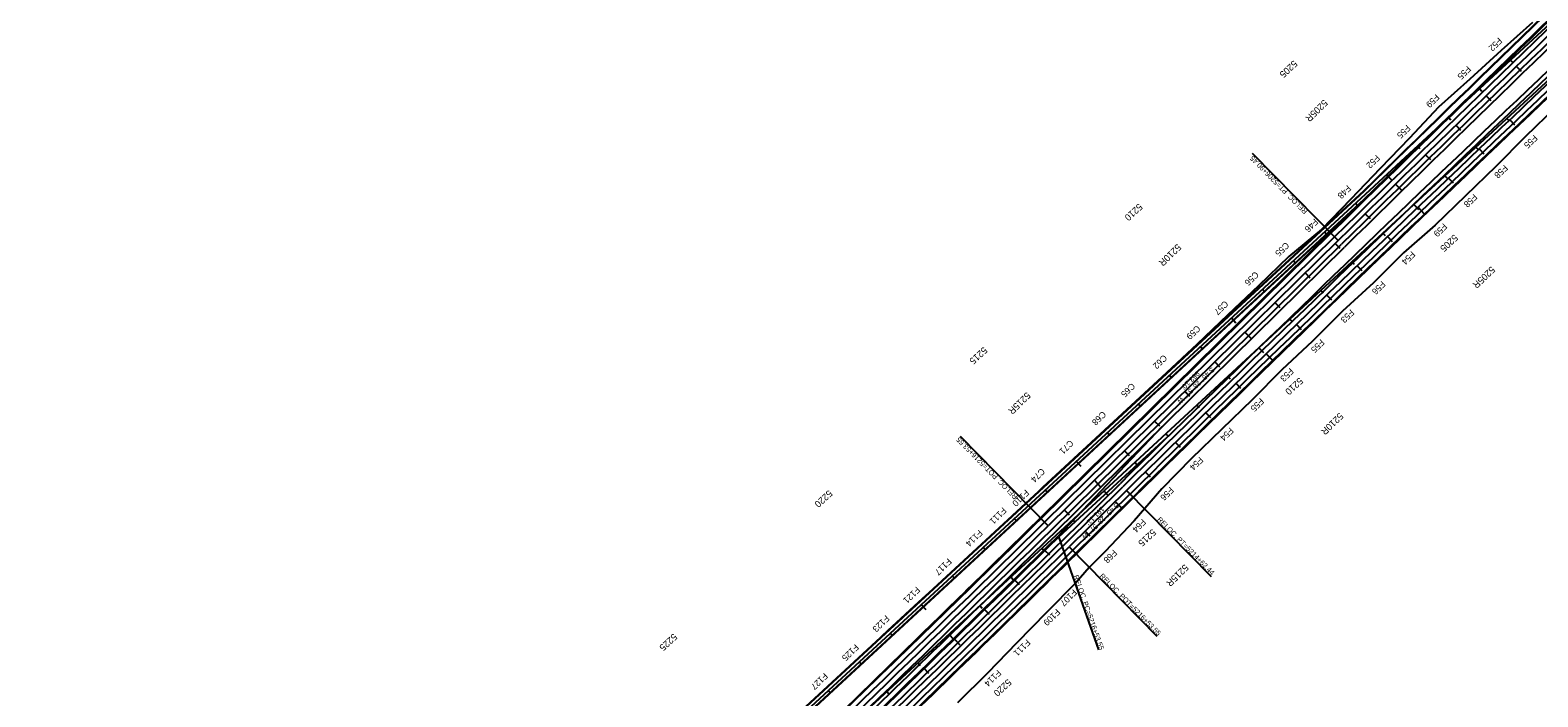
# Model space of a CAD drawing. Extents: x 2160877 to 2175861, y 601747 to 617724.
# Drawn here: x 2166538 to 2170110, y 610271 to 611849 of the extents above; entities that cross this region are included whole.
import ezdxf

# ---------------------------------------------------------------- set-up
doc = ezdxf.new("R2010")
doc.units = 0
for name, color, linetype in [('RD_HC_Cl', 7, 'Continuous'), ('RD_HC_CL_Rel', 7, 'Continuous'), ('RD_HC_Data_Rel', 7, 'Continuous'), ('RD_HC_Data_Tic', 7, 'Continuous'), ('RD_HC_Data_Tic_Rel', 7, 'Continuous'), ('RD_HC_TX_Rel_Sta50', 7, 'Continuous'), ('RD_HC_TX_Rel_StaOther', 7, 'Continuous'), ('RD_HC_TX_StaOther', 7, 'Continuous'), ('RD_PD_CstnLmt', 7, 'Continuous'), ('RD_PD_CstnLmt_TX', 7, 'Continuous'), ('RD_PD_Final_LnLine', 7, 'Continuous'), ('RD_PD_Final_TrvlWay', 7, 'Continuous'), ('RD_PD_GR', 7, 'Continuous'), ('RD_PD_MedBWall', 7, 'Continuous')]:
    doc.layers.add(name, color=color, linetype=linetype)

msp = doc.modelspace()

# ---------------------------------------------------------------- linework, layer by layer
at = {"layer": 'RD_HC_Cl'}
for p, q in [((2172207.3, 613775.1), (2163672.2, 605893.8)), ((2172272.5, 613704.6), (2163737.4, 605823.3))]:
    msp.add_line(p, q, dxfattribs=at)
at = {"layer": 'RD_HC_CL_Rel'}
for p, q in [((2169636.8, 611351.3), (2168950.1, 610676)), ((2169135.7, 610759.9), (2168999.4, 610625.9))]:
    msp.add_line(p, q, dxfattribs=at)
for centre, radius, start, end in [((2222221.5, 557873.6), 75000, 132.719474, 134.517591), ((2219616.9, 559421.3), 72000, 132.719474, 134.517591), ((2118143, 662346), 72500, 312.719474, 314.517591)]:
    msp.add_arc(centre, radius, start, end, dxfattribs=at)
at = {"layer": 'RD_HC_Data_Rel'}
for p, q in [((2169636.8, 611351.3), (2169434.4, 611557.2)), ((2168950.1, 610676), (2168742.3, 610887.4)), ((2169135.7, 610759.9), (2169336.4, 610555.8)), ((2168974.8, 610650.9), (2169069, 610382.3)), ((2168999.4, 610625.9), (2169207.3, 610414.5))]:
    msp.add_line(p, q, dxfattribs=at)
at = {"layer": 'RD_HC_Data_Tic'}
for p, q in [((2170045.3, 611778.7), (2170050.7, 611772.8)), ((2169971.8, 611710.9), (2169977.3, 611705)), ((2169898.4, 611643), (2169903.8, 611637.2)), ((2170037, 611640.3), (2170042.4, 611634.5)), ((2169824.9, 611575.2), (2169830.3, 611569.3)), ((2169963.5, 611572.5), (2169968.9, 611566.6)), ((2169751.4, 611507.4), (2169762.3, 611495.6)), ((2169890, 611504.7), (2169895.4, 611498.8)), ((2169678, 611439.5), (2169683.4, 611433.6)), ((2169816.5, 611436.8), (2169827.4, 611425.1)), ((2169604.5, 611371.7), (2169609.9, 611365.8)), ((2169743.1, 611369), (2169748.5, 611363.1)), ((2169531, 611303.8), (2169536.4, 611298)), ((2169669.6, 611301.1), (2169675, 611295.3)), ((2169457.5, 611236), (2169463, 611230.1)), ((2169596.1, 611233.3), (2169601.6, 611227.4)), ((2169384.1, 611168.1), (2169394.9, 611156.4)), ((2169522.7, 611165.5), (2169528.1, 611159.6)), ((2169310.6, 611100.3), (2169316, 611094.4)), ((2169449.2, 611097.6), (2169460.1, 611085.9)), ((2169237.1, 611032.5), (2169242.6, 611026.6)), ((2169375.7, 611029.8), (2169381.2, 611023.9)), ((2169163.7, 610964.6), (2169169.1, 610958.7)), ((2169302.3, 610961.9), (2169307.7, 610956.1)), ((2169090.2, 610896.8), (2169095.6, 610890.9)), ((2169228.8, 610894.1), (2169234.2, 610888.2)), ((2169016.7, 610828.9), (2169027.6, 610817.2)), ((2169155.3, 610826.3), (2169160.8, 610820.4)), ((2168943.3, 610761.1), (2168948.7, 610755.2)), ((2169081.9, 610758.4), (2169092.7, 610746.7)), ((2168869.8, 610693.3), (2168875.2, 610687.4)), ((2169008.4, 610690.6), (2169013.8, 610684.7)), ((2168796.3, 610625.4), (2168801.8, 610619.5)), ((2168934.9, 610622.7), (2168940.4, 610616.9)), ((2168722.9, 610557.6), (2168728.3, 610551.7)), ((2168861.5, 610554.9), (2168866.9, 610549)), ((2168649.4, 610489.7), (2168660.3, 610478)), ((2168788, 610487.1), (2168793.4, 610481.2)), ((2168575.9, 610421.9), (2168581.4, 610416)), ((2168714.5, 610419.2), (2168725.4, 610407.5)), ((2168502.5, 610354.1), (2168507.9, 610348.2)), ((2168641.1, 610351.4), (2168646.5, 610345.5)), ((2168429, 610286.2), (2168434.4, 610280.3)), ((2168567.6, 610283.5), (2168573, 610277.7))]:
    msp.add_line(p, q, dxfattribs=at)
at = {"layer": 'RD_HC_Data_Tic_Rel'}
for p, q in [((2170059.5, 611763.6), (2170070.6, 611752.1)), ((2169987.7, 611694), (2169998.8, 611682.5)), ((2170043.6, 611637.1), (2170054.6, 611625.5)), ((2169916, 611624.3), (2169927.1, 611612.8)), ((2169844.3, 611554.5), (2169855.5, 611543.1)), ((2169971.1, 611568.2), (2169982.1, 611556.6)), ((2169772.8, 611484.6), (2169786.8, 611470.3)), ((2169898.7, 611499.2), (2169909.8, 611487.6)), ((2169701.4, 611414.7), (2169712.6, 611403.2)), ((2169826.4, 611430.1), (2169840.3, 611415.6)), ((2169630, 611344.6), (2169641.2, 611333.2)), ((2169754.3, 611360.8), (2169765.3, 611349.3)), ((2169558.7, 611274.5), (2169569.9, 611263.1)), ((2169682.2, 611291.5), (2169693.3, 611280)), ((2169487.4, 611204.4), (2169498.6, 611193)), ((2169610.2, 611222.1), (2169621.3, 611210.6)), ((2169416.1, 611134.2), (2169430.1, 611120)), ((2169538.3, 611152.6), (2169549.4, 611141.1)), ((2169344.8, 611064.1), (2169356, 611052.7)), ((2169466.5, 611083), (2169480.4, 611068.7)), ((2169273.5, 610994), (2169284.7, 610982.6)), ((2169394.8, 611013.3), (2169405.9, 611001.9)), ((2169202.2, 610923.9), (2169213.4, 610912.5)), ((2169323.2, 610943.5), (2169334.3, 610932.1)), ((2169130.9, 610853.8), (2169142.1, 610842.4)), ((2169251.6, 610873.6), (2169262.8, 610862.2)), ((2169180.2, 610803.6), (2169191.4, 610792.2)), ((2169059.6, 610783.7), (2169073.6, 610769.4)), ((2169108.9, 610733.5), (2169122.9, 610719.3)), ((2168988.3, 610713.6), (2168999.5, 610702.2)), ((2169037.6, 610663.4), (2169048.8, 610652)), ((2168941.6, 610618.4), (2168952.8, 610607)), ((2168870.2, 610548.4), (2168881.4, 610536.9)), ((2168798.7, 610478.5), (2168809.9, 610467)), ((2168727.2, 610408.6), (2168741.1, 610394.3)), ((2168655.5, 610338.9), (2168666.6, 610327.4))]:
    msp.add_line(p, q, dxfattribs=at)
at = {"layer": 'RD_PD_CstnLmt'}
for p, q in [((2170097.9, 611867.7), (2170023.5, 611800.8)), ((2170023.5, 611800.8), (2169949.4, 611733.5)), ((2169949.4, 611733.5), (2169874.7, 611666.7)), ((2169874.7, 611666.7), (2169805.9, 611593.9)), ((2170152.7, 611667.2), (2170081.3, 611597.4)), ((2169805.9, 611593.9), (2169736.4, 611521.8)), ((2170081.3, 611597.4), (2170010.8, 611526.5)), ((2169736.4, 611521.8), (2169667.5, 611449.2)), ((2170010.8, 611526.5), (2169938.5, 611457.5)), ((2169667.5, 611449.2), (2169598, 611377.1)), ((2169938.5, 611457.5), (2169867, 611387.6)), ((2169598, 611377.1), (2169520.2, 611313.6)), ((2169867, 611387.6), (2169791.6, 611321.9)), ((2169520.2, 611313.6), (2169448.1, 611244.4)), ((2169791.6, 611321.9), (2169721, 611251.2)), ((2169448.1, 611244.4), (2169375.9, 611175.1)), ((2169721, 611251.2), (2169647, 611184)), ((2169375.9, 611175.1), (2169303.4, 611106.2)), ((2169647, 611184), (2169576.5, 611113.2)), ((2169303.4, 611106.2), (2169230, 611038.2)), ((2169576.5, 611113.2), (2169503.4, 611045)), ((2169230, 611038.2), (2169156.6, 610970.3)), ((2169503.4, 611045), (2169433.2, 610973.9)), ((2169156.6, 610970.3), (2169083.2, 610902.3)), ((2169433.2, 610973.9), (2169361.1, 610904.6)), ((2169083.2, 610902.3), (2169009.8, 610834.3)), ((2169361.1, 610904.6), (2169289.3, 610835.1)), ((2169009.8, 610834.3), (2168936.4, 610766.3)), ((2169289.3, 610835.1), (2169219.5, 610763.6)), ((2168936.4, 610766.3), (2168897.9, 610729.1)), ((2169219.5, 610763.6), (2169153.6, 610688.1)), ((2168863.8, 610697.6), (2168790.5, 610629.8)), ((2168897.9, 610729.1), (2168863.8, 610697.6)), ((2169153.6, 610688.1), (2169085, 610615.2)), ((2168790.5, 610629.8), (2168717.1, 610562.1)), ((2169085, 610615.2), (2169047, 610577.5)), ((2168717.1, 610562.1), (2168642.8, 610495.3)), ((2169047, 610577.5), (2169016.7, 610542)), ((2169016.7, 610542), (2168946.2, 610470.8)), ((2168642.8, 610495.3), (2168569.6, 610427.3)), ((2168946.2, 610470.8), (2168876.1, 610399.2)), ((2168569.6, 610427.3), (2168497, 610358.8)), ((2168876.1, 610399.2), (2168806.6, 610327)), ((2168497, 610358.8), (2168423.6, 610291.1)), ((2168806.6, 610327), (2168735.1, 610256.9))]:
    msp.add_line(p, q, dxfattribs=at)
at = {"layer": 'RD_PD_Final_LnLine'}
for p, q in [((2168941.7, 610684.6), (2169628.4, 611359.8)), ((2168958.5, 610667.5), (2169645.3, 611342.7)), ((2169219.5, 610910), (2168973.9, 610651.8)), ((2168975.6, 610650.1), (2169242.4, 610895.4)), ((2168991, 610634.4), (2169127.3, 610768.4)), ((2169007.8, 610617.3), (2169144.1, 610751.3))]:
    msp.add_line(p, q, dxfattribs=at)
for centre, radius, start, end in [((2222221.5, 557873.6), 75012, 132.719474, 134.517591), ((2222221.5, 557873.6), 74988, 132.719474, 134.517591), ((2219616.9, 559421.3), 72012, 132.719474, 134.517591), ((2219616.9, 559421.3), 71988, 132.719474, 134.517591), ((2118143, 662346), 72452.8, 312.719474, 314.517591), ((2118143, 662346), 72464.8, 312.719474, 314.517591), ((2118143, 662346), 72476.8, 312.719474, 314.517591), ((2118143, 662346), 72498.8, 312.719474, 314.517591), ((2118143, 662346), 72501.2, 312.719474, 314.517591), ((2118143, 662346), 72523.2, 312.719474, 314.517591), ((2118143, 662346), 72535.2, 312.719474, 314.517591), ((2118143, 662346), 72547.2, 312.719474, 314.517591)]:
    msp.add_arc(centre, radius, start, end, dxfattribs=at)
at = {"layer": 'RD_PD_Final_TrvlWay'}
for p, q in [((2168931.7, 610694.8), (2169618.4, 611370.1)), ((2168933.3, 610693.2), (2169620.1, 611368.4)), ((2168965.5, 610660.3), (2169652.3, 611335.6)), ((2168984, 610641.6), (2169120.3, 610775.6)), ((2169014.8, 610610.2), (2169151.1, 610744.2)), ((2168465.3, 610238.6), (2168608.1, 610378.6))]:
    msp.add_line(p, q, dxfattribs=at)
for centre, radius, start, end in [((2222220.1, 557875.1), 75024.3, 132.719474, 134.517591), ((2222220.1, 557875.1), 75022, 132.719474, 134.517591), ((2222221.5, 557873.6), 74978, 132.719474, 134.517591), ((2219616.9, 559421.3), 72022, 132.719474, 134.517591), ((2219616.9, 559421.3), 71978, 132.719474, 134.517591), ((2118141.6, 662347.5), 72442.8, 314.001538, 314.517591), ((2118143, 662346), 72486.8, 313.983529, 314.517591), ((2118141.6, 662347.5), 72440.5, 314.159761, 314.517591), ((2118143, 662346), 72513.2, 313.98353, 314.517591), ((2118143, 662346), 72557.2, 314.001574, 314.517591)]:
    msp.add_arc(centre, radius, start, end, dxfattribs=at)
at = {"layer": 'RD_PD_GR'}
msp.add_line((2169016.3, 610608.8), (2169152.5, 610742.8), dxfattribs=at)
for centre, radius, start, end in [((2219616.9, 559421.3), 71976, 132.719474, 134.517591), ((2118143, 662346), 72559.2, 313.996755, 314.517591)]:
    msp.add_arc(centre, radius, start, end, dxfattribs=at)
at = {"layer": 'RD_PD_MedBWall'}
for p, q in [((2169697.9, 611469.1), (2165055.7, 607182.5)), ((2169698.6, 611468.4), (2165056.4, 607181.7)), ((2169708.3, 611458.3), (2165065.8, 607171.5)), ((2169684.4, 611434.9), (2165066.5, 607170.7))]:
    msp.add_line(p, q, dxfattribs=at)
for radius, end in [(75039.3, 134.421287), (75038.3, 134.421298)]:
    msp.add_arc((2222220.1, 557875.1), radius, 132.719474, end, dxfattribs=at)

# ---------------------------------------------------------------- texts
at = {"layer": 'RD_HC_Data_Rel'}
for s, rotation, p in [('RELOC. PT=5206+90.45', 134.5176, (2169565.3, 611421.2)), ('RELOC. POT=5216+53.55', 134.5176, (2168878.6, 610745.9)), ('RELOC. PT=5214+62.44', 314.5176, (2169207.2, 610690)), ('RELOC. PC=5216+53.55', 289.3225, (2169009.7, 610557.2)), ('RELOC. POT=5216+53.55', 314.5176, (2169071, 610556))]:
    msp.add_text(s, height=12, rotation=rotation, dxfattribs=at).set_placement(p)
at = {"layer": 'RD_HC_TX_Rel_Sta50'}
for s, rotation, p in [('5205R', 224.3721, (2169603, 611686.3)), ('5210R', 224.5176, (2169255.7, 611344.6)), ('5205R', 223.7517, (2169999.8, 611291.5)), ('5215R', 224.5176, (2168898.9, 610993.8)), ('5210R', 224.1496, (2169640, 610944.9)), ('5215R', 224.5176, (2169273.2, 610586.2))]:
    msp.add_text(s, height=16, rotation=rotation, dxfattribs=at).set_placement(p)
at = {"layer": 'RD_HC_TX_Rel_StaOther'}
for s, p in [('S 45%%d 28\' 57" W', (2169337.4, 611052.6)), ("963.10'", (2169302.1, 611043.2)), ('S 45%%d 28\' 57" W', (2169111.5, 610731.8)), ("191.11'", (2169076.2, 610722.4))]:
    msp.add_text(s, height=12, rotation=224.5176, dxfattribs=at).set_placement(p)
at = {"layer": 'RD_HC_TX_StaOther'}
for s, p in [('5205', (2169531.6, 611779.1)), ('5210', (2169164.6, 611440.3)), ('5205', (2169912, 611367.1)), ('5215', (2168796.9, 611100.7)), ('5210', (2169545, 611028.2)), ('5220', (2168429.9, 610761.8)), ('5215', (2169196.7, 610669.6)), ('5225', (2168062.2, 610422.3)), ('5220', (2168854.2, 610314.6))]:
    msp.add_text(s, height=16, rotation=222.7195, dxfattribs=at).set_placement(p)
at = {"layer": 'RD_PD_CstnLmt_TX'}
for s, rotation, p in [('F52', 224.0665, (2170017, 611832.9)), ('F55', 224.1429, (2169943, 611765.8)), ('F59', 224.2193, (2169868.3, 611699.1)), ('F55', 224.2957, (2169799.6, 611626.2)), ('F55', 223.513, (2170100.8, 611602.7)), ('F52', 224.3721, (2169727.1, 611555.5)), ('F58', 223.5926, (2170030.4, 611531.8)), ('F48', 224.4485, (2169658.9, 611483.5)), ('F58', 223.6721, (2169958.1, 611462.9)), ('F46', 224.5176, (2169580.9, 611404.4)), ('F59', 223.7517, (2169886.6, 611393.1)), ('C55', 224.5176, (2169512.4, 611348.7)), ('F54', 223.8313, (2169811, 611327.2)), ('C56', 224.5176, (2169440.2, 611279.3)), ('F56', 223.9109, (2169740.5, 611256.6)), ('C57', 224.5176, (2169368, 611210.1)), ('F53', 223.9904, (2169666.5, 611189.5)), ('C59', 224.5176, (2169301.9, 611151.8)), ('F55', 224.07, (2169596, 611118.7)), ('C62', 224.5176, (2169223.1, 611082.2)), ('F53', 224.1496, (2169523, 611050.5)), ('C65', 224.5176, (2169147.3, 611015.4)), ('F55', 224.2292, (2169452.7, 610979.5)), ('C68', 224.5176, (2169078.5, 610948.6)), ('C71', 224.5176, (2169001.2, 610880.4)), ('F54', 224.3087, (2169380.5, 610910)), ('F54', 224.3883, (2169308.6, 610840.6)), ('C74', 224.5176, (2168933.7, 610813.6)), ('F56', 224.4679, (2169238.9, 610769.2)), ('F110', 224.5176, (2168896.1, 610763)), ('F111', 224.4809, (2168842.5, 610720.8)), ('F114', 224.4019, (2168785.8, 610667.8)), ('F64', 224.5176, (2169172.9, 610693.6)), ('F117', 224.3228, (2168712.5, 610600.2)), ('F68', 224.5176, (2169104.5, 610620.9)), ('F121', 224.2438, (2168637.8, 610533)), ('F107', 224.4809, (2169009.4, 610526.9)), ('F123', 224.1648, (2168565.2, 610465.5)), ('F109', 224.4019, (2168969.7, 610480.5)), ('F125', 224.0857, (2168492.6, 610397)), ('F111', 224.3228, (2168899.2, 610408.3)), ('F127', 224.0067, (2168419.2, 610329.1)), ('F114', 224.2438, (2168830, 610336.4))]:
    msp.add_text(s, height=15, rotation=rotation, dxfattribs=at).set_placement(p)

doc.saveas('drawing.dxf')
